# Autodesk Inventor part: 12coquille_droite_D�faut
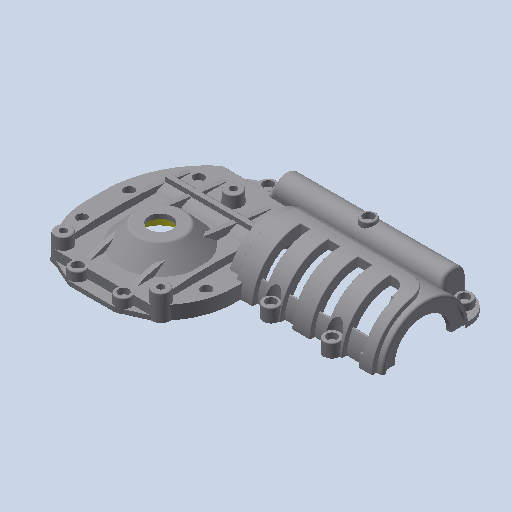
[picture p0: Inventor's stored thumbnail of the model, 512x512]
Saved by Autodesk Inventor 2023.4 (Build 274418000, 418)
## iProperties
Created: 2011-01
Part Number: 12coquille_droite_D�faut
Document SubType Name: Modeling
Designer: eric
Density: 1 g/cm^3
Mass: 223.119 g
Surface Area: 1202.09 cm^2
Volume: 223.119 cm^3
Material: Générique
Appearance: Par défaut
Author: eric
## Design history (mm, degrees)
feature "Base1"
node "Corps solides"
node "Corps surfaciques"
node "Solide1"
